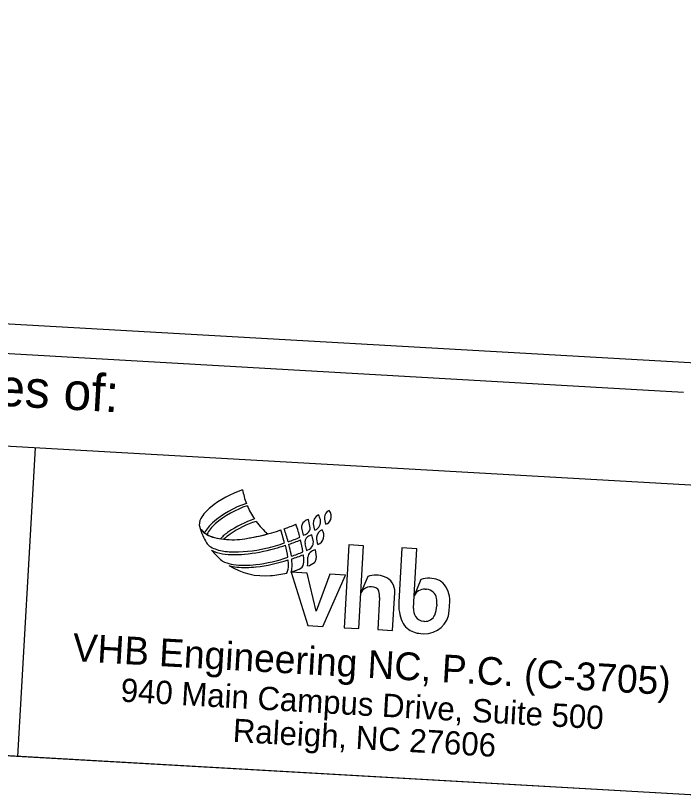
# Model space of a CAD drawing. Extents: x 2601627 to 2606907, y 616646 to 620530.
# Drawn here: x 2605115.1 to 2605451.9, y 617444.1 to 617837.9 of the extents above; entities that cross this region are included whole.
import ezdxf

# ---------------------------------------------------------------- set-up
doc = ezdxf.new("R2010")
doc.units = 0
doc.layers.add('Sheet Title CELL', color=7, linetype='Continuous')
doc.layers.add('Stewart Logo', color=7, linetype='Continuous')

msp = doc.modelspace()

# ---------------------------------------------------------------- linework, layer by layer
at = {"layer": 'Sheet Title CELL'}
for p, q in [((2602382.68, 617837.86), (2606635.79, 617595.63)), ((2604598.24, 617696.65), (2605451.86, 617648.03)), ((2605125.01, 617619.86), (2605116.15, 617464.31)), ((2605470.29, 617444.12), (2604950.78, 617473.73))]:
    msp.add_line(p, q, dxfattribs=at)
msp.add_lwpolyline([(2604556.77, 617496.18), (2605470.29, 617444.15), (2605479.15, 617599.69), (2604565.63, 617651.72)], close=True, dxfattribs=at)
at = {"layer": 'Stewart Logo'}
for p, q in [((2605263.7, 617579.63), (2605262.8, 617583.71)), ((2605259.31, 617579.5), (2605260.11, 617575.87)), ((2605250.8, 617571.97), (2605248.86, 617578.46)), ((2605265.27, 617572.42), (2605264.49, 617575.97)), ((2605261.06, 617571.45), (2605261.79, 617568.16)), ((2605283.11, 617570.95), (2605280.73, 617529.19)), ((2605290.64, 617570.53), (2605283.11, 617570.95)), ((2605309.91, 617569.43), (2605308.35, 617542.04)), ((2605317.45, 617569), (2605309.91, 617569.43)), ((2605254.14, 617557.22), (2605258.08, 617558.7)), ((2605262.19, 617556.76), (2605254.14, 617557.22)), ((2605254.14, 617557.22), (2605262.55, 617530.23)), ((2605266.77, 617537.56), (2605262.19, 617556.76)), ((2605273.51, 617556.11), (2605266.77, 617537.56)), ((2605281.56, 617555.66), (2605273.51, 617556.11)), ((2605270.14, 617529.79), (2605281.56, 617555.66)), ((2605292.7, 617555.02), (2605289.29, 617546.84)), ((2605319.5, 617553.49), (2605316.1, 617545.31)), ((2605321.62, 617548.58), (2605322.33, 617548.54)), ((2605298.63, 617544.38), (2605297.71, 617528.22)), ((2605305.24, 617527.79), (2605306.33, 617546.96)), ((2605327.59, 617540.96), (2605327.54, 617540.14)), ((2605333.77, 617537.67), (2605334.05, 617542.45)), ((2605321.37, 617532.38), (2605320.89, 617532.41)), ((2605262.55, 617530.23), (2605270.14, 617529.79)), ((2605280.73, 617529.19), (2605288.26, 617528.76)), ((2605297.71, 617528.22), (2605305.24, 617527.79)), ((2605319.44, 617526.26), (2605320.89, 617526.17))]:
    msp.add_line(p, q, dxfattribs=at)
for points in [[(2605288.26, 617528.76), (2605289.29, 617546.84), (2605290.64, 617570.53)], [(2605315.73, 617538.89), (2605316.1, 617545.31), (2605317.45, 617569)]]:
    msp.add_lwpolyline(points, dxfattribs=at)
for centre, major_axis, start_param, end_param in [((2605246.14, 617549.31), (52.04, -2.96), 1.950459, 2.306295), ((2605267.41, 617605.47), (38.34, -2.18), 3.374816, 3.559712), ((2605247.85, 617543.86), (50.67, -2.89), 1.955908, 2.345415), ((2605226.68, 617573.44), (21.09, -1.2), 2.306295, 2.663056), ((2605247.85, 617543.86), (49.38, -2.81), 1.954608, 2.331375), ((2605267.41, 617605.47), (38.34, -2.18), 3.593328, 3.791245), ((2605274.44, 617584.89), (3.56, -0.2), 1.950799, 3.19085), ((2605269.34, 617585.33), (4.93, -0.28), 6.010502, 6.978239), ((2605213.23, 617581.41), (5.48, -0.31), 2.663056, 3.487291), ((2605253.3, 617532.1), (54.78, -3.12), 1.956929, 2.223843), ((2605263.63, 617579.12), (4.66, -0.27), 1.805558, 2.340862), ((2605269.88, 617581.86), (4.66, -0.27), 2.069357, 3.26373), ((2605264.27, 617582.66), (4.66, -0.27), 5.158115, 6.583255), ((2605260.01, 617581.6), (9.04, -0.51), 0.300085, 0.573578), ((2605279.93, 617584.85), (9.04, -0.51), 3.190836, 3.597778), ((2605270.38, 617584.97), (3.83, -0.22), 5.088672, 6.010509), ((2605240.84, 617589.62), (34.24, -1.95), 3.487291, 3.49224), ((2605210.64, 617580.48), (2.74, -0.16), 3.492238, 3.942132), ((2605210.64, 617580.48), (2.74, -0.16), 3.492238, 3.942132), ((2605240.84, 617589.62), (34.24, -1.95), 3.492238, 3.737263), ((2605227.1, 617567.62), (19.17, -1.09), 2.345415, 2.685879), ((2605227.38, 617567.98), (17.8, -1.01), 2.331375, 2.717794), ((2605253.3, 617532.1), (53.38, -3.04), 1.949325, 2.223843), ((2605267.41, 617605.47), (38.34, -2.18), 3.829221, 4.05458), ((2605213.88, 617682.46), (109.55, -6.24), 5.110242, 5.168312), ((2605120.5, 617535.52), (143.3, -8.16), 0.355324, 0.381952), ((2605263, 617579.85), (3.7, -0.21), 2.340862, 3.293303), ((2605260, 617579.73), (3.7, -0.21), 5.445151, 6.311085), ((2605274.26, 617582.14), (9.04, -0.51), 3.26373, 3.631752), ((2605218.52, 617587.73), (13.42, -0.76), 3.942115, 4.117328), ((2605218.52, 617587.73), (13.42, -0.76), 3.942115, 4.535322), ((2605218.52, 617587.73), (13.42, -0.76), 4.225969, 4.535322), ((2605236.36, 617557.07), (24.65, -1.4), 2.223843, 2.440018), ((2605236.36, 617557.07), (23.25, -1.32), 2.223843, 2.396036), ((2605213.88, 617682.46), (109.55, -6.24), 4.923489, 5.093727), ((2605213.88, 617682.46), (109.55, -6.24), 4.923489, 5.030725), ((2605120.5, 617535.52), (136.94, -7.8), 0.330018, 0.379866), ((2605190.07, 617556.92), (70.63, -4.02), 0.312292, 0.355324), ((2605259.4, 617580.48), (4.66, -0.27), 4.922279, 5.445148), ((2605265.58, 617570.87), (5.2, -0.3), 1.838184, 2.294391), ((2605271.3, 617574.47), (4.38, -0.25), 1.982585, 3.114577), ((2605264.82, 617575.65), (5.75, -0.33), 6.124862, 6.873863), ((2605216.12, 617574.84), (5.48, -0.31), 3.737263, 4.155114), ((2605224.62, 617613.34), (39.71, -2.26), 4.535322, 4.613027), ((2605224.62, 617613.34), (39.71, -2.26), 4.535322, 4.657076), ((2605224.62, 617613.34), (39.71, -2.26), 4.657076, 4.923489), ((2605224.62, 617613.34), (39.71, -2.26), 4.657076, 4.923489), ((2605213.88, 617682.46), (116.32, -6.63), 5.007435, 5.091777), ((2605213.88, 617682.46), (116.37, -6.63), 5.107726, 5.162272), ((2605213.88, 617682.46), (117.69, -6.7), 5.106941, 5.160619), ((2605190.07, 617556.92), (70.63, -4.02), 0.205325, 0.293478), ((2605264.56, 617572.17), (3.56, -0.2), 2.294387, 3.400315), ((2605261.71, 617572.16), (3.56, -0.2), 5.669754, 6.410867), ((2605274.58, 617574.19), (7.67, -0.44), 3.114567, 3.617561), ((2605265.89, 617575.42), (4.66, -0.27), 5.137017, 6.124854), ((2605219.59, 617579.77), (11.5, -0.66), 4.155114, 4.433304), ((2605221.96, 617583.32), (16.98, -0.97), 4.281835, 4.626581), ((2605240.84, 617589.62), (34.24, -1.95), 3.869789, 4.084312), ((2605224.12, 617592.72), (25.2, -1.44), 4.433304, 4.717272), ((2605226.16, 617631.89), (64.36, -3.67), 4.717272, 5.007435), ((2605222, 617653.6), (87.64, -4.99), 4.866042, 5.043468), ((2605213.88, 617682.46), (117.58, -6.7), 5.043468, 5.091439), ((2605214.37, 617559.77), (38.34, -2.18), 0.186675, 0.34709), ((2605120.5, 617535.52), (136.94, -7.8), 0.309699, 0.320394), ((2605214.37, 617559.77), (40.15, -2.29), 0.192744, 0.309699), ((2605260.42, 617573.19), (5.2, -0.3), 5.034707, 5.66976), ((2605268.39, 617561.1), (7.67, -0.44), 1.905419, 2.288613), ((2605253.35, 617564.83), (13.42, -0.76), 6.258511, 6.615609), ((2605226.05, 617611.83), (45.74, -2.61), 4.626581, 4.866042), ((2605225.86, 617642.62), (82.17, -4.68), 4.896065, 5.098239), ((2605213.88, 617682.46), (123.8, -7.05), 5.100586, 5.150688), ((2605213.88, 617682.46), (125.14, -7.13), 5.098273, 5.148033), ((2605214.37, 617559.77), (40.15, -2.29), 0.08898, 0.158557), ((2605190.07, 617556.92), (70.63, -4.02), 0.162521, 0.185756), ((2605249.51, 617563.22), (10.96, -0.62), 6.17953, 6.445706), ((2605239.8, 617563.12), (22.73, -1.29), 6.218327, 6.411973), ((2605265.53, 617564.78), (3.01, -0.17), 2.288613, 3.208516), ((2605263.79, 617564.34), (3.01, -0.17), 5.49053, 6.137671), ((2605222.62, 617567.31), (5.48, -0.31), 4.084312, 4.375641), ((2605227.35, 617578.71), (17.8, -1.01), 4.375641, 4.631331), ((2605229.16, 617584.9), (25.2, -1.44), 4.511808, 4.670453), ((2605240.84, 617589.62), (34.24, -1.95), 4.213149, 4.853258), ((2605230.82, 617603.71), (43, -2.45), 4.631331, 4.896065), ((2605231.28, 617606.19), (46.56, -2.65), 4.670453, 4.878361), ((2605227.99, 617636.19), (76.69, -4.37), 4.878361, 5.095384), ((2605244.53, 617560.49), (8.22, -0.47), 5.862276, 6.364042), ((2605214.37, 617559.77), (38.34, -2.18), 0.080866, 0.152313), ((2605240.85, 617560.62), (13.69, -0.78), 6.089473, 6.37216), ((2605256.82, 617562.04), (3.56, -0.2), 5.129856, 6.17953), ((2605260.71, 617567.85), (7.67, -0.44), 4.991009, 5.49053), ((2605238.77, 617614.22), (58.89, -3.35), 4.853258, 4.99278), ((2605296.72, 617542.92), (12.74, -0.73), 1.271815, 1.948427), ((2605298.39, 617547.42), (7.94, -0.45), 6.283185, 7.555001), ((2605323.52, 617541.39), (12.74, -0.73), 1.243417, 1.948427), ((2605325.84, 617547.11), (6.57, -0.37), 0.841181, 1.243417), ((2605321.86, 617543.14), (12.19, -0.69), 0, 0.841181), ((2605294.36, 617544.09), (-5.75, 0.33), 4.330931, 5.84316), ((2605295.64, 617546.82), (-2.74, 0.16), 3.478495, 4.330931), ((2605321.3, 617542.83), (5.75, -0.33), 1.570796, 2.75299), ((2605322.01, 617543.06), (5.48, -0.31), 0.218399, 1.570796), ((2605289.04, 617544.93), (9.59, -0.55), 0, 0.336903), ((2605313.89, 617541.74), (13.69, -0.78), 6.283185, 6.501584), ((2605330.27, 617540.79), (-21.91, 1.25), 0, 0.452165), ((2605313.85, 617540.92), (13.69, -0.78), 5.93764, 6.283185), ((2605322.58, 617538.5), (-6.85, 0.39), 6.283185, 6.906012), ((2605321.59, 617538.36), (12.19, -0.69), 4.712389, 6.283185), ((2605318.11, 617535.72), (-8.76, 0.5), 0.452165, 0.946963), ((2605321.19, 617537.61), (-5.2, 0.3), 0.622827, 1.570796), ((2605321.67, 617537.59), (5.2, -0.3), 4.712389, 5.93764), ((2605320.12, 617538.2), (-11.94, 0.68), 0.946963, 1.570796)]:
    msp.add_ellipse(centre, major_axis=major_axis, ratio=0.999914, start_param=start_param, end_param=end_param, dxfattribs=at)

# ---------------------------------------------------------------- texts
at = {"layer": 'Sheet Title CELL'}
msp.add_text('Prepared in the Offices of:', height=18.75, rotation=356.7403, dxfattribs=at).set_placement((2604875.93, 617654.34))
at = {"layer": 'Stewart Logo'}
for s, height, rotation, p in [('VHB Engineering NC, P.C. (C-3705)', 14.0105, 356.7398, (2605143.59, 617512.37)), ('940 Main Campus Drive, Suite 500', 11.7567, 356.701, (2605167.89, 617491.93)), ('Raleigh, NC 27606', 11.7567, 356.701, (2605224.43, 617471.64))]:
    msp.add_text(s, height=height, rotation=rotation, dxfattribs=at).set_placement(p)

doc.saveas('drawing.dxf')
